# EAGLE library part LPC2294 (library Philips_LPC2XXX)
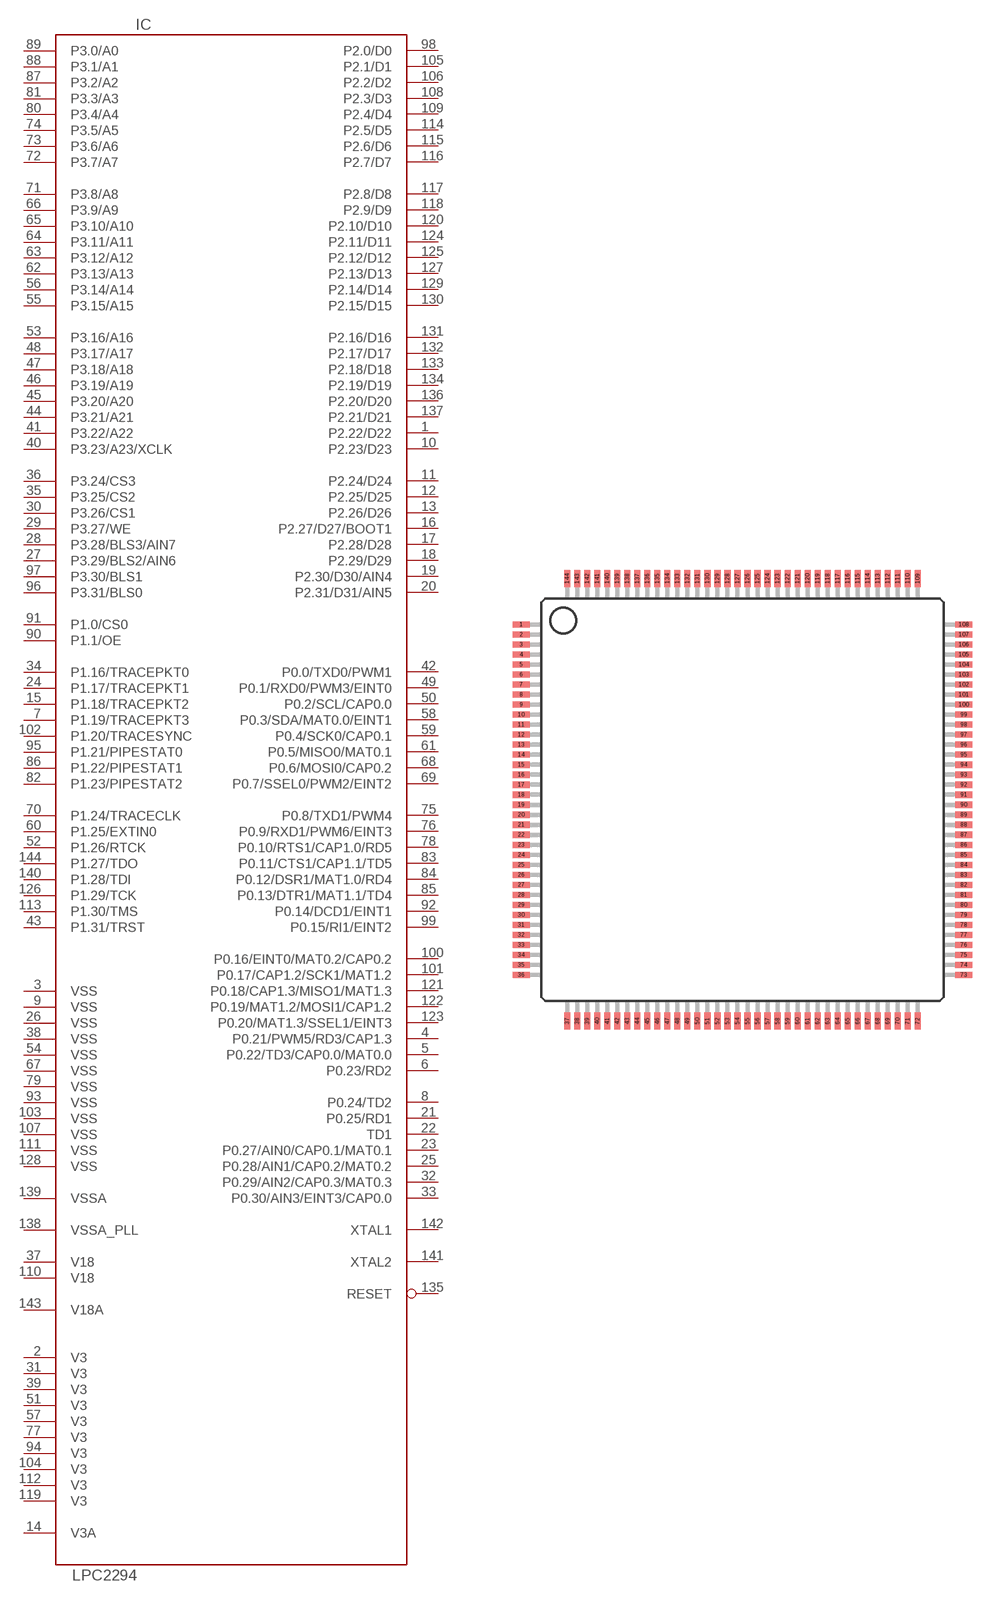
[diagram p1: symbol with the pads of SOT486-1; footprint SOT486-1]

Designator prefix IC

## LPC2294  [SOT486-1]
1  P2.22/D22
2  V3  pwr
3  VSS  pwr
4  P0.21/PWM5/RD3/CAP1.3
5  P0.22/TD3/CAP0.0/MAT0.0
6  P0.23/RD2
7  P1.19/TRACEPKT3
8  P0.24/TD2
9  VSS  pwr
10  P2.23/D23
11  P2.24/D24
12  P2.25/D25
13  P2.26/D26
14  V3A  pwr
15  P1.18/TRACEPKT2
16  P2.27/D27/BOOT1
17  P2.28/D28
18  P2.29/D29
19  P2.30/D30/AIN4
20  P2.31/D31/AIN5
21  P0.25/RD1
22  TD1
23  P0.27/AIN0/CAP0.1/MAT0.1
24  P1.17/TRACEPKT1
25  P0.28/AIN1/CAP0.2/MAT0.2
26  VSS  pwr
27  P3.29/BLS2/AIN6
28  P3.28/BLS3/AIN7
29  P3.27/WE
30  P3.26/CS1
31  V3  pwr
32  P0.29/AIN2/CAP0.3/MAT0.3
33  P0.30/AIN3/EINT3/CAP0.0
34  P1.16/TRACEPKT0
35  P3.25/CS2
36  P3.24/CS3
37  V18  pwr
38  VSS  pwr
39  V3  pwr
40  P3.23/A23/XCLK
41  P3.22/A22
42  P0.0/TXD0/PWM1
43  P1.31/TRST
44  P3.21/A21
45  P3.20/A20
46  P3.19/A19
47  P3.18/A18
48  P3.17/A17
49  P0.1/RXD0/PWM3/EINT0
50  P0.2/SCL/CAP0.0
51  V3  pwr
52  P1.26/RTCK
53  P3.16/A16
54  VSS  pwr
55  P3.15/A15
56  P3.14/A14
57  V3  pwr
58  P0.3/SDA/MAT0.0/EINT1
59  P0.4/SCK0/CAP0.1
60  P1.25/EXTIN0
61  P0.5/MISO0/MAT0.1
62  P3.13/A13
63  P3.12/A12
64  P3.11/A11
65  P3.10/A10
66  P3.9/A9
67  VSS  pwr
68  P0.6/MOSI0/CAP0.2
69  P0.7/SSEL0/PWM2/EINT2
70  P1.24/TRACECLK
71  P3.8/A8
72  P3.7/A7
73  P3.6/A6
74  P3.5/A5
75  P0.8/TXD1/PWM4
76  P0.9/RXD1/PWM6/EINT3
77  V3  pwr
78  P0.10/RTS1/CAP1.0/RD5
79  VSS  pwr
80  P3.4/A4
81  P3.3/A3
82  P1.23/PIPESTAT2
83  P0.11/CTS1/CAP1.1/TD5
84  P0.12/DSR1/MAT1.0/RD4
85  P0.13/DTR1/MAT1.1/TD4
86  P1.22/PIPESTAT1
87  P3.2/A2
88  P3.1/A1
89  P3.0/A0
90  P1.1/OE
91  P1.0/CS0
92  P0.14/DCD1/EINT1
93  VSS  pwr
94  V3  pwr
95  P1.21/PIPESTAT0
96  P3.31/BLS0
97  P3.30/BLS1
98  P2.0/D0
99  P0.15/RI1/EINT2
100  P0.16/EINT0/MAT0.2/CAP0.2
101  P0.17/CAP1.2/SCK1/MAT1.2
102  P1.20/TRACESYNC
103  VSS  pwr
104  V3  pwr
105  P2.1/D1
106  P2.2/D2
107  VSS  pwr
108  P2.3/D3
109  P2.4/D4
110  V18  pwr
111  VSS  pwr
112  V3  pwr
113  P1.30/TMS
114  P2.5/D5
115  P2.6/D6
116  P2.7/D7
117  P2.8/D8
118  P2.9/D9
119  V3  pwr
120  P2.10/D10
121  P0.18/CAP1.3/MISO1/MAT1.3
122  P0.19/MAT1.2/MOSI1/CAP1.2
123  P0.20/MAT1.3/SSEL1/EINT3
124  P2.11/D11
125  P2.12/D12
126  P1.29/TCK
127  P2.13/D13
128  VSS  pwr
129  P2.14/D14
130  P2.15/D15
131  P2.16/D16
132  P2.17/D17
133  P2.18/D18
134  P2.19/D19
135  RESET
136  P2.20/D20
137  P2.21/D21
138  VSSA_PLL  pwr
139  VSSA  pwr
140  P1.28/TDI
141  XTAL2
142  XTAL1
143  V18A  pwr
144  P1.27/TDO

## Footprint SOT486-1 (pad centres in mm)
smd 0.864 x 0.305: 1 -11,8.6; 2 -11,8.1; 3 -11,7.6; 4 -11,7.1; 5 -11,6.6; 6 -11,6.1; 7 -11,5.6; 8 -11,5.1; 9 -11,4.6; 10 -11,4.1; 11 -11,3.6; 12 -11,3.1; 13 -11,2.6; 14 -11,2.1; 15 -11,1.6; 16 -11,1.1; 17 -11,0.6; 18 -11,0.1; 19 -11,-0.4; 20 -11,-0.9; 21 -11,-1.4; 22 -11,-1.9; 23 -11,-2.4; 24 -11,-2.9; 25 -11,-3.4; 26 -11,-3.9; 27 -11,-4.4; 28 -11,-4.9; 29 -11,-5.4; 30 -11,-5.9; 31 -11,-6.4; 32 -11,-6.9; 33 -11,-7.4; 34 -11,-7.9; 35 -11,-8.4; 36 -11,-8.9; 73 11.1,-8.9; 74 11.1,-8.4; 75 11.1,-7.9; 76 11.1,-7.4; 77 11.1,-6.9; 78 11.1,-6.4; 79 11.1,-5.9; 80 11.1,-5.4; 81 11.1,-4.9; 82 11.1,-4.4; 83 11.1,-3.9; 84 11.1,-3.4; 85 11.1,-2.9; 86 11.1,-2.4; 87 11.1,-1.9; 88 11.1,-1.4; 89 11.1,-0.9; 90 11.1,-0.4; 91 11.1,0.1; 92 11.1,0.6; 93 11.1,1.1; 94 11.1,1.6; 95 11.1,2.1; 96 11.1,2.6; 97 11.1,3.1; 98 11.1,3.6; 99 11.1,4.1; 100 11.1,4.6; 101 11.1,5.1; 102 11.1,5.6; 103 11.1,6.1; 104 11.1,6.6; 105 11.1,7.1; 106 11.1,7.6; 107 11.1,8.1; 108 11.1,8.6
smd 0.305 x 0.864: 37 -8.7,-11.2; 38 -8.2,-11.2; 39 -7.7,-11.2; 40 -7.2,-11.2; 41 -6.7,-11.2; 42 -6.2,-11.2; 43 -5.7,-11.2; 44 -5.2,-11.2; 45 -4.7,-11.2; 46 -4.2,-11.2; 47 -3.7,-11.2; 48 -3.2,-11.2; 49 -2.7,-11.2; 50 -2.2,-11.2; 51 -1.7,-11.2; 52 -1.2,-11.2; 53 -0.7,-11.2; 54 -0.2,-11.2; 55 0.3,-11.2; 56 0.8,-11.2; 57 1.3,-11.2; 58 1.8,-11.2; 59 2.3,-11.2; 60 2.8,-11.2; 61 3.3,-11.2; 62 3.8,-11.2; 63 4.3,-11.2; 64 4.8,-11.2; 65 5.3,-11.2; 66 5.8,-11.2; 67 6.3,-11.2; 68 6.8,-11.2; 69 7.3,-11.2; 70 7.8,-11.2; 71 8.3,-11.2; 72 8.8,-11.2; 109 8.8,10.9; 110 8.3,10.9; 111 7.8,10.9; 112 7.3,10.9; 113 6.8,10.9; 114 6.3,10.9; 115 5.8,10.9; 116 5.3,10.9; 117 4.8,10.9; 118 4.3,10.9; 119 3.8,10.9; 120 3.3,10.9; 121 2.8,10.9; 122 2.3,10.9; 123 1.8,10.9; 124 1.3,10.9; 125 0.8,10.9; 126 0.3,10.9; 127 -0.2,10.9; 128 -0.7,10.9; 129 -1.2,10.9; 130 -1.7,10.9; 131 -2.2,10.9; 132 -2.7,10.9; 133 -3.2,10.9; 134 -3.7,10.9; 135 -4.2,10.9; 136 -4.7,10.9; 137 -5.2,10.9; 138 -5.7,10.9; 139 -6.2,10.9; 140 -6.7,10.9; 141 -7.2,10.9; 142 -7.7,10.9; 143 -8.2,10.9; 144 -8.7,10.9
